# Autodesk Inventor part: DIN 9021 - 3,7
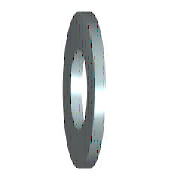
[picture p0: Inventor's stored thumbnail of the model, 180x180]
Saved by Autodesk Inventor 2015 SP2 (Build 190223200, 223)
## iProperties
IsCustomPart: 0
Created: 2012-02
Part Number: DIN 9021 - 3,7
Material: Stahl, weich
Description: Unterlegscheibe
Document SubType Name: Modeling
Standard: DIN 9021
Designer: Hübner
Standards Organization: DIN
Language: de-DE
Size Designation: 3,7
Categories: <MemberInstance><Categories><Category DisplayName="Verbindungselemente" InternalName="e4da775c-781d-43d5-af7c-5136215cf5a6" Mnemonic="FSTN"><Category DisplayNam
Density: 7.85 g/cm^3
Appearance: Halbpoliert
Author: Hübner
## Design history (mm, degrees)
sketch "Skizze"
  geometry: C1 r 5.5 at (0, 0); C2 r 1.85 at (0, 0); 1 further point
  constraints: 2 centre point, 2 coincident
  dimensions: "d0" = 3.7 diameter of C2 (= SD1); "d1" = 11 diameter of C1 (= SD2)
extrude "Körper" new body sketch "Skizze" distance "d2" = 0.8 (= SD); taper "d3" = 0 deg
workaxis "Work Axis1"
workplane "Work Plane1"
body "Solid1"
other parameters: "SD1" = 3.7 [user parameter; used in 1 equation term], "SD2" = 11 [user parameter; used in 1 equation term], "SD" = 0.8 [user parameter; used in 1 equation term], "d4" = 0, "d5" = 0, "d6" = 0, "d7" = 0, "NND" = 3.5 [user parameter]
